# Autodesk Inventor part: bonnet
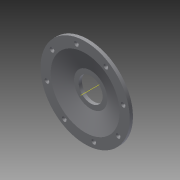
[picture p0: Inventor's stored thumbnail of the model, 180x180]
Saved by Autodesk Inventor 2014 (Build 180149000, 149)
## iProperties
Created: 2002-09
Part Number: bonnet
Document SubType Name: Modeling
Designer: ales
Density: 1 g/cm^3
Material: Generic
Appearance: Default
Control State: 0
Master: False
Checked Out: False
Shininess: 64.0
Length Units: 11269
Angle Units: 11279
Time Units: 11290
Mass Units: 11283
Length Display Precision: 3
Angle Display Precision: 2
Density: 0.0
Volumn: 0.0
Area: 0.0
PropertySet Name: Model Information
Author: PaulN
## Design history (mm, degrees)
sketch "Sketch1"
  geometry: C1 r 74.5 at (0, 0) reference; C2 r 96.5 at (0, 0)
  constraints: 1 centre point, 1 coincident
  dimensions: "d24" = 22 radial gap between concentric circles of C1 C2
extrude "Extrusion1" new body sketch "Sketch1" distance "d0" = 7; taper "d1" = 0 deg
workplane "Work Plane1"
workaxis "Work Axis2"
sketch "Sketch2"
  geometry: L1 (23.857, 0)-(23.857, -36); C1 r 26 at (23.857, 0) reference; C2 r 74.5 at (23.857, 0) reference; 1 further point
  constraints: 2 end point, 1 vertical, 1 vertical alignment, 3 other
  dimensions: "d25" = 10 dimension on C1
extrude "Extrusion2" join sketch "Sketch2" distance "d4" = 7; taper "d5" = 0 deg
workplane "Work Plane2"
sketch "Sketch3"
  geometry: L1 (74.5, 5)-(74.5, 12) reference; L2 (36, 0)-(36, -7) reference; L3 (36, 0)-(74.5, 12); L4 (36, -7)-(74.5, 5); L5 (0, -10.8)-(0, 15.8) reference
  constraints: 4 end point, 1 parallel
revolve "Revolution1" sketch "Sketch3" stored, may be unused: angle "d7" = 90 deg
sketch "Sketch5"
  geometry: C1 r 3 at (82.385, 18.789) reference
extrude "Extrusion3" cut sketch "Sketch5" stored distance "d26" = 10; taper "d27" = 0 deg
chamfer "Chamfer2" distance "d28" = 2; stored, may be unused: second distance "d29" = 2, angle "d33" = 45 deg
pattern_circular "Circular Pattern2" dims angle "d32" = 360 deg
body "Solid1"
node "Reference6"
node "Reference7"
